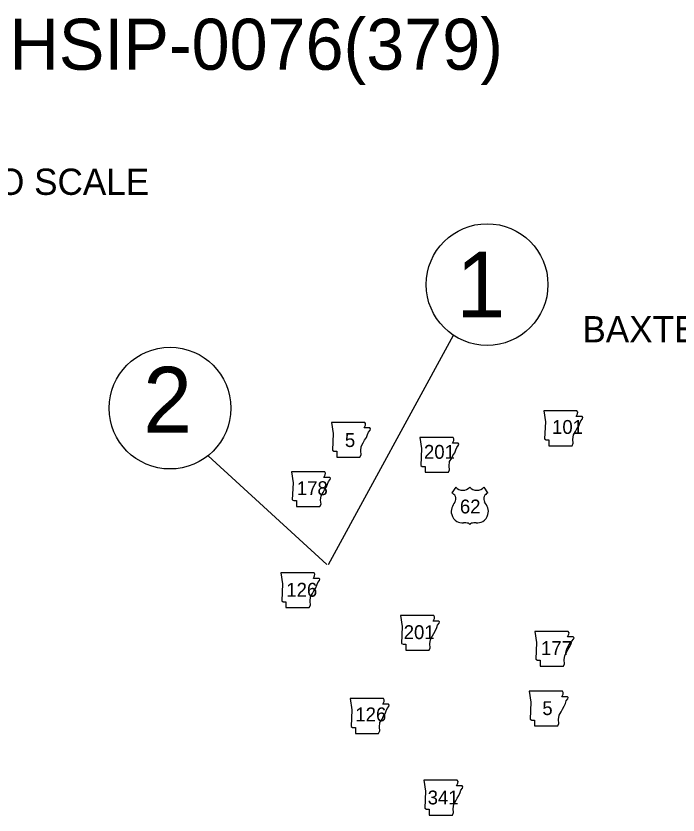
# Model space of a CAD drawing. Extents: x -819161 to 80911, y -6604 to 768454.
# Drawn here: x 43651 to 45921, y 5004 to 7744 of the extents above; entities that cross this region are included whole.
import ezdxf

# ---------------------------------------------------------------- set-up
doc = ezdxf.new("R2010")
doc.units = 0
for name, color, linetype in [('Default', 7, 'Continuous'), ('Level 21', 7, 'Continuous'), ('Level 22', 7, 'Continuous')]:
    doc.layers.add(name, color=color, linetype=linetype)

msp = doc.modelspace()

# ---------------------------------------------------------------- linework, layer by layer
at = {"layer": 'Default'}
for points in [[(44722.6, 5863.1), (45150.9, 6649)], [(44309.5, 6236), (44717, 5862.9)]]:
    msp.add_lwpolyline(points, dxfattribs=at)
for centre in [(45266.6, 6822.7), (44179.2, 6399)]:
    msp.add_circle(centre, 208.7, dxfattribs=at)
at = {"layer": 'Level 21'}
for points in [[(45460.7, 6389.6), (45466.4, 6351.5), (45463.9, 6293.8), (45469, 6290.6), (45478.5, 6290.6), (45478.5, 6270.3), (45558.4, 6270.3), (45562.2, 6278.6), (45561, 6291.9), (45562.9, 6307.1), (45569.8, 6319.2), (45574.3, 6328), (45580.6, 6337.6), (45584.4, 6347.7), (45587.6, 6356), (45593.3, 6362.9), (45594.6, 6367.4), (45592.1, 6370.5), (45572.4, 6370.5), (45576.8, 6379.4), (45577.5, 6385.1), (45574.8, 6389.5)], [(44732.9, 6350.3), (44738.6, 6312.2), (44736.1, 6254.5), (44741.1, 6251.3), (44750.7, 6251.3), (44750.7, 6231), (44830.6, 6231), (44834.4, 6239.3), (44833.1, 6252.6), (44835, 6267.8), (44842, 6279.9), (44846.4, 6288.8), (44852.8, 6298.3), (44856.6, 6308.4), (44859.8, 6316.7), (44865.5, 6323.6), (44866.8, 6328.1), (44864.2, 6331.3), (44844.5, 6331.3), (44849, 6340.1), (44849.6, 6345.8), (44847, 6350.2)], [(45036, 6298.1), (45041.7, 6260.1), (45039.1, 6202.3), (45044.2, 6199.2), (45053.7, 6199.2), (45053.7, 6178.9), (45133.7, 6178.9), (45137.5, 6187.1), (45136.2, 6200.4), (45138.1, 6215.7), (45145.1, 6227.7), (45149.5, 6236.6), (45155.9, 6246.1), (45159.7, 6256.3), (45162.9, 6264.5), (45168.6, 6271.5), (45169.8, 6275.9), (45167.3, 6279.1), (45147.6, 6279.1), (45152.1, 6288), (45152.7, 6293.7), (45150.1, 6298.1)], [(44595.5, 6180.6), (44601.2, 6142.6), (44598.6, 6084.8), (44603.7, 6081.7), (44613.2, 6081.7), (44613.2, 6061.4), (44693.2, 6061.4), (44697, 6069.6), (44695.7, 6082.9), (44697.6, 6098.2), (44704.6, 6110.2), (44709, 6119.1), (44715.4, 6128.6), (44719.2, 6138.8), (44722.3, 6147), (44728.1, 6154), (44729.3, 6158.4), (44726.8, 6161.6), (44707.1, 6161.6), (44711.6, 6170.5), (44712.2, 6176.2), (44709.6, 6180.6)], [(44559, 5834.2), (44564.8, 5796.1), (44562.2, 5738.4), (44567.3, 5735.2), (44576.8, 5735.2), (44576.8, 5714.9), (44656.7, 5714.9), (44660.5, 5723.2), (44659.3, 5736.5), (44661.2, 5751.7), (44668.2, 5763.8), (44672.6, 5772.7), (44678.9, 5782.2), (44682.8, 5792.3), (44685.9, 5800.6), (44691.6, 5807.6), (44692.9, 5812), (44690.4, 5815.2), (44670.7, 5815.2), (44675.1, 5824.1), (44675.8, 5829.8), (44673.1, 5834.2)], [(44970, 5688.1), (44975.7, 5650), (44973.1, 5592.3), (44978.2, 5589.1), (44987.7, 5589.1), (44987.7, 5568.8), (45067.7, 5568.8), (45071.5, 5577.1), (45070.2, 5590.4), (45072.1, 5605.6), (45079.1, 5617.7), (45083.5, 5626.5), (45089.9, 5636.1), (45093.7, 5646.2), (45096.8, 5654.5), (45102.6, 5661.4), (45103.8, 5665.9), (45101.3, 5669), (45081.6, 5669), (45086.1, 5677.9), (45086.7, 5683.6), (45084.1, 5688)], [(45430.8, 5633.5), (45436.5, 5595.4), (45434, 5537.7), (45439.1, 5534.5), (45448.6, 5534.5), (45448.6, 5514.2), (45528.5, 5514.2), (45532.3, 5522.4), (45531.1, 5535.8), (45533, 5551), (45539.9, 5563), (45544.4, 5571.9), (45550.7, 5581.4), (45554.5, 5591.6), (45557.7, 5599.8), (45563.4, 5606.8), (45564.7, 5611.3), (45562.1, 5614.4), (45542.5, 5614.4), (45546.9, 5623.3), (45547.6, 5629), (45544.9, 5633.4)], [(45411.2, 5428.4), (45416.9, 5390.4), (45414.3, 5332.6), (45419.4, 5329.5), (45428.9, 5329.5), (45428.9, 5309.2), (45508.9, 5309.2), (45512.7, 5317.4), (45511.4, 5330.7), (45513.3, 5345.9), (45520.3, 5358), (45524.7, 5366.9), (45531.1, 5376.4), (45534.9, 5386.6), (45538.1, 5394.8), (45543.8, 5401.8), (45545, 5406.2), (45542.5, 5409.4), (45522.8, 5409.4), (45527.3, 5418.3), (45527.9, 5424), (45525.3, 5428.4)], [(44797, 5402.9), (44802.7, 5364.8), (44800.2, 5307.1), (44805.3, 5303.9), (44814.8, 5303.9), (44814.8, 5283.6), (44894.7, 5283.6), (44898.5, 5291.8), (44897.3, 5305.2), (44899.2, 5320.4), (44906.2, 5332.4), (44910.6, 5341.3), (44916.9, 5350.8), (44920.7, 5361), (44923.9, 5369.2), (44929.6, 5376.2), (44930.9, 5380.7), (44928.4, 5383.8), (44908.7, 5383.8), (44913.1, 5392.7), (44913.8, 5398.4), (44911.1, 5402.8)], [(45050, 5122.9), (45055.8, 5084.9), (45053.2, 5027.1), (45058.3, 5024), (45067.8, 5024), (45067.8, 5003.7), (45147.7, 5003.7), (45151.6, 5011.9), (45150.3, 5025.2), (45152.2, 5040.4), (45159.2, 5052.5), (45163.6, 5061.4), (45169.9, 5070.9), (45173.8, 5081.1), (45176.9, 5089.3), (45182.6, 5096.3), (45183.9, 5100.7), (45181.4, 5103.9), (45161.7, 5103.9), (45166.1, 5112.8), (45166.8, 5118.5), (45164.1, 5122.9)]]:
    msp.add_lwpolyline(points, close=True, dxfattribs=at)
at = {"layer": 'Level 22'}
for p, q in [((45159, 6128.5), (45146, 6108.4)), ((45255.5, 6128.5), (45268.5, 6108.4))]:
    msp.add_line(p, q, dxfattribs=at)
for centre, radius, start, end in [((45183.1, 6148.8), 31.6, 220.075, 319.6701), ((45231.3, 6148.8), 31.6, 220.3299, 319.925), ((45129, 6079.3), 33.7, 30.7809, 59.9883), ((45136.4, 6088.2), 23.1, 328.8105, 21.2108), ((45278, 6088.2), 23.1, 158.7892, 211.1895), ((45285.4, 6079.3), 33.7, 120.0117, 149.2191), ((45179.1, 6045.2), 35.6, 160.9576, 197.3819), ((45196.9, 6040.8), 53.9, 138.9565, 162.6913), ((45217.5, 6040.8), 53.9, 17.3087, 41.0435), ((45235.4, 6045.2), 35.6, 342.6181, 19.0424), ((45184.9, 6045.3), 41.2, 195.1074, 237.1312), ((45229.6, 6045.3), 41.2, 302.8688, 344.8926), ((45185.7, 6058.3), 53, 244.0771, 269.5779), ((45186.9, 5908.4), 97, 81.1942, 90.9539), ((45199, 5995.3), 9.29, 28.0342, 72.9864), ((45215.4, 5995.3), 9.29, 107.0136, 151.9658), ((45227.6, 5908.4), 97, 89.0461, 98.8058), ((45228.8, 6058.3), 53, 270.4221, 295.9229)]:
    msp.add_arc(centre, radius, start, end, dxfattribs=at)

# ---------------------------------------------------------------- texts
at = {"layer": 'Default'}
for s, height, p in [('FED. AID PROJ. HSIP-0076(379)', 175.134, (41820, 7559.4)), ('NOT TO SCALE', 90, (43225.1, 7130.4)), ('1', 225.4, (45160.9, 6710)), ('BAXTER COUNTY', 90, (45593.3, 6624.6)), ('2', 225.4, (44087.1, 6315.2))]:
    msp.add_text(s, height=height, dxfattribs=at).set_placement(p)
at = {"layer": 'Level 21'}
for s, height, p in [('101', 47.52, (45489.4, 6310.7)), ('5', 47.5, (44778.9, 6265.7)), ('201', 47.52, (45050.1, 6225.3)), ('178', 47.52, (44614.1, 6100.6)), ('126', 47.52, (44578, 5752.3)), ('201', 47.52, (44980.6, 5607)), ('177', 47.52, (45451.3, 5552.4)), ('126', 47.52, (44814.8, 5324.9)), ('5', 47.5, (45456, 5346.4)), ('341', 47.52, (45062.8, 5040))]:
    msp.add_text(s, height=height, dxfattribs=at).set_placement(p)
at = {"layer": 'Level 22'}
msp.add_text('62', height=47.52, dxfattribs=at).set_placement((45173.3, 6037.9))

doc.saveas('drawing.dxf')
